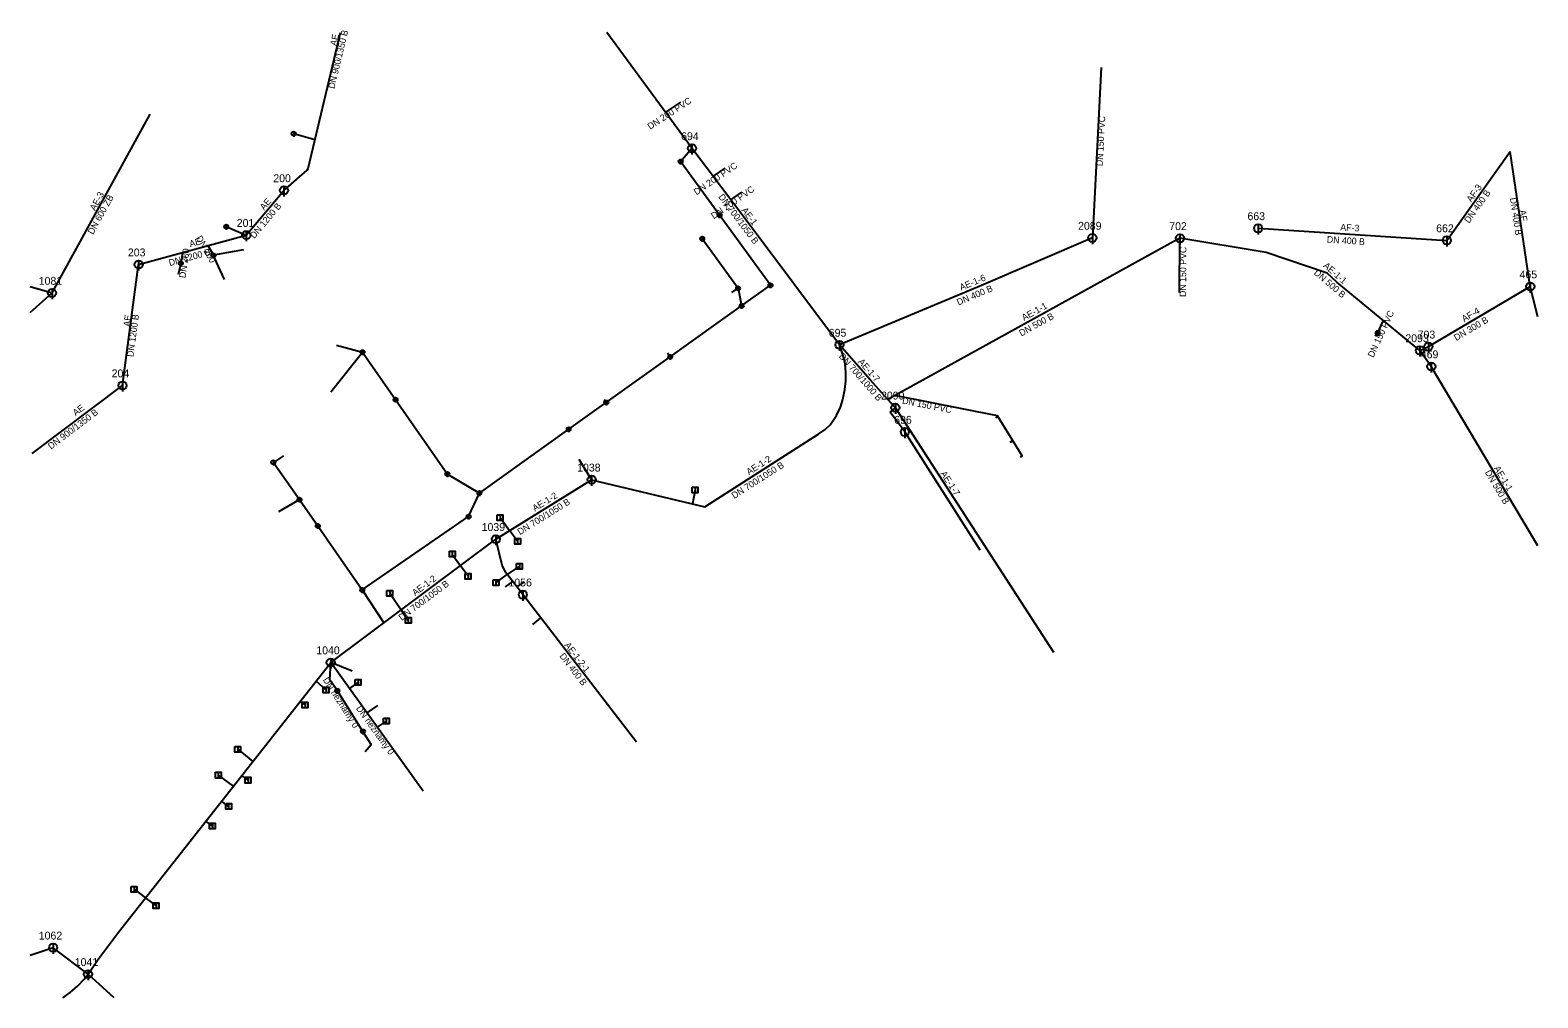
# Model space of a CAD drawing. Extents: x -4927513 to -4923824, y -11264917 to -11262549.
import ezdxf

# ---------------------------------------------------------------- set-up
doc = ezdxf.new("R2010")
doc.units = 0
for name, color, linetype in [('_pripojka_kanal_destova_priblizne_', 7, 'Continuous'), ('_pripojka_kanal_jednotna_prevzato_z_dokumentace_', 7, 'Continuous'), ('_pripojka_kanal_jednotna_priblizne_', 7, 'Continuous'), ('_pripojka_kanal_splaskova_priblizne_', 7, 'Continuous'), ('_stoka_jednotna_smvak_prevzato_z_dokumentace_', 7, 'Continuous'), ('_stoka_jednotna_smvak_priblizne_', 7, 'Continuous'), ('Default', 7, 'Continuous'), ('MoLevel 1', 7, 'Continuous'), ('MoLevel 119', 7, 'Continuous'), ('MoLevel 120', 7, 'Continuous'), ('MoLevel 124', 7, 'Continuous'), ('MoLevel 126', 7, 'Continuous'), ('MoLevel 2', 7, 'Continuous'), ('MoLevel 57', 7, 'Continuous'), ('MoLevel 60', 7, 'Continuous'), ('MoLevel 63', 7, 'Continuous'), ('MoLevel 68', 7, 'Continuous'), ('MoLevel 69', 7, 'Continuous')]:
    doc.layers.add(name, color=color, linetype=linetype)

# ---------------------------------------------------------------- blocks, each defined once
blk = doc.blocks.new('_vpust_')
at = {"layer": 'Default'}
blk.add_line((0, 0.00025), (0, -0.00025), dxfattribs=at)
blk.add_lwpolyline([(-0.00035, 0.00035), (0.00035, 0.00035), (0.00035, -0.00035), (-0.00035, -0.00035), (-0.00035, 0.00035)], dxfattribs=at)
blk = doc.blocks.new('_sachta_kanal_prip_')
at = {"layer": 'Default'}
blk.add_line((0, 0.0005), (0, -0.00075), dxfattribs=at)
blk.add_circle((0, 0), 0.0005, dxfattribs=at)
blk = doc.blocks.new('_sachta_kanal_prevzato_z_dokumentace_')
at = {"layer": 'Default'}
blk.add_line((0, 0.0005), (0, -0.00075), dxfattribs=at)
blk.add_circle((0, 0), 0.0005, dxfattribs=at)

msp = doc.modelspace()

# ---------------------------------------------------------------- linework, layer by layer
at = {"layer": '_pripojka_kanal_destova_priblizne_'}
for p, q in [((-4925150.4, -11263497.6), (-4925146, -11263492.5)), ((-4926170.4, -11263598.6), (-4926139.5, -11263648.9)), ((-4925886.4, -11263673.9), (-4925892.7, -11263708)), ((-4926363.5, -11263741.6), (-4926340.1, -11263773.6)), ((-4926320.6, -11263799.5), (-4926340.1, -11263773.6)), ((-4926480.6, -11263831), (-4926460.5, -11263859.3)), ((-4926441.7, -11263885.2), (-4926460.5, -11263859.3)), ((-4926373.5, -11263900.9), (-4926345.8, -11263880.7)), ((-4926316.3, -11263860.9), (-4926345.8, -11263880.7)), ((-4926633.4, -11263926.9), (-4926605.7, -11263967.6)), ((-4926588, -11263993.1), (-4926605.7, -11263967.6)), ((-4926725.7, -11264117.3), (-4926777.9, -11264096.1)), ((-4926789.4, -11264163.8), (-4926813.9, -11264141.9)), ((-4926710.9, -11264144.6), (-4926732.2, -11264159.7)), ((-4926840.6, -11264200.2), (-4926852.4, -11264190.8)), ((-4926641.9, -11264239.5), (-4926664.3, -11264254.2)), ((-4927005.6, -11264308.5), (-4926968.5, -11264338.2)), ((-4927053.1, -11264371.9), (-4927016.3, -11264399)), ((-4926980.3, -11264384.2), (-4926995.7, -11264372.8)), ((-4927027.9, -11264448.4), (-4927045, -11264435.3)), ((-4927067.4, -11264496.4), (-4927083.6, -11264484.4)), ((-4927259.1, -11264651.2), (-4927231.4, -11264672.2)), ((-4927205.4, -11264691.2), (-4927231.4, -11264672.2))]:
    msp.add_line(p, q, dxfattribs=at)
at = {"layer": '_pripojka_kanal_jednotna_prevzato_z_dokumentace_'}
for p, q in [((-4927033.6, -11263029.7), (-4926984.4, -11263050.4)), ((-4927078.7, -11263076.2), (-4927065.1, -11263099.9)), ((-4927141, -11263093.2), (-4927144.6, -11263119.7))]:
    msp.add_line(p, q, dxfattribs=at)
at = {"layer": '_pripojka_kanal_jednotna_priblizne_'}
for p, q in [((-4924892.2, -11262639.9), (-4924914.1, -11263057.3)), ((-4925922.3, -11262725.5), (-4925958.9, -11262749.5)), ((-4926868.5, -11262802.2), (-4926816.6, -11262816.8)), ((-4925921.6, -11262870.2), (-4925893.8, -11262838)), ((-4925826.2, -11263001.7), (-4925921.6, -11262870.2)), ((-4925813.4, -11262886.8), (-4925842.3, -11262906.5)), ((-4925772.8, -11262945.5), (-4925799.2, -11262963.8)), ((-4925701.8, -11263173.1), (-4925826.2, -11263001.7)), ((-4925868.7, -11263059), (-4925781, -11263180.4)), ((-4924700.7, -11263190.8), (-4924699.8, -11263058.1)), ((-4927144.6, -11263119.7), (-4927150.9, -11263147.2)), ((-4925796.5, -11263191.1), (-4925781, -11263180.4)), ((-4925781, -11263180.4), (-4925772.3, -11263223.4)), ((-4925772.3, -11263223.4), (-4925701.8, -11263173.1)), ((-4925947.1, -11263348.2), (-4925772.3, -11263223.4)), ((-4924222.1, -11263296.6), (-4924215.7, -11263289.5)), ((-4926777.8, -11263434.1), (-4926700.1, -11263336.6)), ((-4926763.4, -11263319.4), (-4926700.1, -11263336.6)), ((-4926700.1, -11263336.6), (-4926619.1, -11263452.9)), ((-4925953.9, -11263338.5), (-4925947.1, -11263348.2)), ((-4926103.5, -11263459.8), (-4925947.1, -11263348.2)), ((-4926195.4, -11263525.4), (-4926103.5, -11263459.8)), ((-4926109, -11263452.5), (-4926103.5, -11263459.8)), ((-4926414.1, -11263681.5), (-4926195.4, -11263525.4)), ((-4926893.4, -11263590.8), (-4926918.3, -11263606.5)), ((-4926918.3, -11263606.5), (-4926854.2, -11263697.6)), ((-4926492.3, -11263635), (-4926414.1, -11263681.5)), ((-4926904.7, -11263727.1), (-4926854.2, -11263697.6)), ((-4926854.2, -11263697.6), (-4926809.4, -11263762)), ((-4926700.8, -11263918.8), (-4926440.4, -11263739.1)), ((-4926809.4, -11263762), (-4926700.8, -11263918.8)), ((-4926700.8, -11263918.8), (-4926647.8, -11263999)), ((-4926349.9, -11263911.4), (-4926332.2, -11263898.1)), ((-4926304.1, -11263898.6), (-4926322.1, -11263911.4)), ((-4926283.2, -11264003), (-4926263.8, -11263987.2)), ((-4926551.5, -11264411.2), (-4926777.9, -11264096.1))]:
    msp.add_line(p, q, dxfattribs=at)
for points in [[(-4926991.2, -11263086.2), (-4927028.1, -11263092.6), (-4927065.1, -11263099.9)], [(-4927037.8, -11263158.7), (-4927057.5, -11263116.8), (-4927065.1, -11263099.9)], [(-4924215.7, -11263289.5), (-4924208.3, -11263273.2), (-4924201.7, -11263259.2)], [(-4925090.1, -11263592.8), (-4925086, -11263590.2), (-4925146, -11263492.5), (-4925397.1, -11263442.9)], [(-4926619.1, -11263452.9), (-4926492.4, -11263635), (-4926492.3, -11263635)], [(-4926440.4, -11263739.1), (-4926440.4, -11263739.1), (-4926414.1, -11263681.5)]]:
    msp.add_lwpolyline(points, dxfattribs=at)
at = {"layer": '_pripojka_kanal_splaskova_priblizne_'}
for p, q in [((-4925115.6, -11263556.7), (-4925108.8, -11263553.1)), ((-4926699, -11264264.8), (-4926761.7, -11264165.4)), ((-4926663.7, -11264201.2), (-4926689.3, -11264219.4))]:
    msp.add_line(p, q, dxfattribs=at)
for points in [[(-4926761.7, -11264165.4), (-4926779.9, -11264139), (-4926777.9, -11264096.1)], [(-4926693.9, -11264314.2), (-4926678.7, -11264297), (-4926699, -11264264.8)]]:
    msp.add_lwpolyline(points, dxfattribs=at)
at = {"layer": '_stoka_jednotna_smvak_prevzato_z_dokumentace_'}
for p, q in [((-4925893.8, -11262838), (-4926102.1, -11262554.7)), ((-4927459.8, -11263192), (-4927220.1, -11262754.5)), ((-4924046.6, -11263063.4), (-4923891.9, -11262845.8)), ((-4923842.4, -11263176.3), (-4923891.9, -11262845.8)), ((-4926984.4, -11263050.4), (-4926892.3, -11262940.9)), ((-4924508.3, -11263033.8), (-4924046.6, -11263063.4)), ((-4927248, -11263122.4), (-4926984.4, -11263050.4)), ((-4927287.4, -11263418.4), (-4927248, -11263122.4)), ((-4927513.4, -11263176.3), (-4927459.8, -11263192)), ((-4927513.4, -11263240.1), (-4927459.8, -11263192)), ((-4923823.9, -11263250.2), (-4923842.4, -11263176.3)), ((-4924084.6, -11263371.8), (-4924112.8, -11263332.4)), ((-4923823.9, -11263810.7), (-4924084.6, -11263371.8)), ((-4927508.4, -11263584.9), (-4927287.4, -11263418.4)), ((-4925372.9, -11263532), (-4925408.8, -11263483.9)), ((-4925188.6, -11263821.2), (-4925372.9, -11263532)), ((-4926373.7, -11263794.5), (-4926139.5, -11263648.9)), ((-4926777.9, -11264096.1), (-4926373.7, -11263794.5)), ((-4926029.8, -11264291), (-4926307.7, -11263930.1)), ((-4927457, -11264794.1), (-4927513.4, -11264813.2)), ((-4927371.7, -11264858.9), (-4927457, -11264794.1)), ((-4927371.7, -11264858.9), (-4927348.8, -11264824.4)), ((-4927307.6, -11264916.8), (-4927371.7, -11264858.9))]:
    msp.add_line(p, q, dxfattribs=at)
for points in [[(-4925533, -11263319), (-4925756.6, -11263020.4), (-4925893.8, -11262838)], [(-4926892.3, -11262940.9), (-4926835.8, -11262891.7), (-4926833.3, -11262887.3)], [(-4924914.1, -11263057.3), (-4925190.7, -11263175.8), (-4925533, -11263319)], [(-4926307.7, -11263930.1), (-4926349.9, -11263875.1), (-4926358.5, -11263858.4), (-4926373.7, -11263794.5)], [(-4927348.8, -11264824.4), (-4927297.3, -11264755.9), (-4926777.9, -11264096.1)], [(-4927433.5, -11264916.8), (-4927415.7, -11264904.1), (-4927396.7, -11264887.4), (-4927381, -11264870.9), (-4927371.7, -11264858.9)]]:
    msp.add_lwpolyline(points, dxfattribs=at)
at = {"layer": '_stoka_jednotna_smvak_priblizne_'}
for p, q in [((-4926833.3, -11262887.3), (-4926754.3, -11262554.7)), ((-4924699.8, -11263058.1), (-4925414.7, -11263452.6)), ((-4924091.8, -11263323.4), (-4923842.4, -11263176.3)), ((-4924112.8, -11263332.4), (-4924091.8, -11263323.4)), ((-4925396, -11263472.8), (-4925414.7, -11263452.6)), ((-4925408.8, -11263483.9), (-4925396, -11263472.8)), ((-4925008.4, -11264071.9), (-4925396, -11263472.8))]:
    msp.add_line(p, q, dxfattribs=at)
for points in [[(-4924112.8, -11263332.4), (-4924315.7, -11263165.3), (-4924339.8, -11263143.6), (-4924488.9, -11263093), (-4924699.8, -11263058.1)], [(-4926139.5, -11263648.9), (-4925862.7, -11263715.2), (-4925583.1, -11263536.8), (-4925567.7, -11263526.3), (-4925555.6, -11263514.6), (-4925540.1, -11263492.1), (-4925530.4, -11263471.4), (-4925524.3, -11263452.7), (-4925519.6, -11263428.3), (-4925517.3, -11263406.9), (-4925517.1, -11263388), (-4925518.4, -11263374.3), (-4925520, -11263359.5), (-4925522.9, -11263348.6), (-4925526.4, -11263337.7), (-4925533, -11263319)], [(-4925414.7, -11263452.6), (-4925430.4, -11263435.6), (-4925456.7, -11263405.4), (-4925533, -11263319)]]:
    msp.add_lwpolyline(points, dxfattribs=at)

# ---------------------------------------------------------------- block references
at = {"layer": 'MoLevel 119', "xscale": 20000, "yscale": 20000}
for p in [(-4925893.8, -11262838), (-4926892.3, -11262940.9), (-4926984.4, -11263050.4), (-4924508.3, -11263033.8), (-4924914.1, -11263057.3), (-4924699.8, -11263058.1), (-4924046.6, -11263063.4), (-4927248, -11263122.4), (-4927459.8, -11263192), (-4923842.4, -11263176.3), (-4925533, -11263319), (-4924112.8, -11263332.4), (-4924091.8, -11263323.4), (-4924084.6, -11263371.8), (-4927287.4, -11263418.4), (-4925396, -11263472.8), (-4925372.9, -11263532), (-4926139.5, -11263648.9), (-4926373.7, -11263794.5), (-4926307.7, -11263930.1), (-4926777.9, -11264096.1), (-4927457, -11264794.1), (-4927371.7, -11264858.9)]:
    msp.add_blockref('_sachta_kanal_prevzato_z_dokumentace_', p, dxfattribs=at)
at = {"layer": 'MoLevel 57', "xscale": 10000, "yscale": 10000}
for p in [(-4926868.5, -11262802.2), (-4925921.6, -11262870.2), (-4925826.2, -11263001.7), (-4927033.6, -11263029.7), (-4925868.7, -11263059), (-4927144.6, -11263119.7), (-4927065.1, -11263099.9), (-4925781, -11263180.4), (-4925701.8, -11263173.1), (-4925772.3, -11263223.4), (-4924215.7, -11263289.5), (-4926700.1, -11263336.6), (-4925947.1, -11263348.2), (-4926619.1, -11263452.9), (-4926103.5, -11263459.8), (-4926195.4, -11263525.4), (-4926918.3, -11263606.5), (-4926492.4, -11263635), (-4926854.2, -11263697.6), (-4926414.1, -11263681.5), (-4926440.4, -11263739.1), (-4926809.4, -11263762), (-4926700.8, -11263918.8), (-4926761.7, -11264165.4), (-4926699, -11264264.8)]:
    msp.add_blockref('_sachta_kanal_prip_', p, dxfattribs=at)
at = {"layer": 'MoLevel 63', "xscale": 20000, "yscale": 20000}
for p in [(-4925886.4, -11263673.9), (-4926363.5, -11263741.6), (-4926320.6, -11263799.5), (-4926480.6, -11263831), (-4926316.3, -11263860.9), (-4926441.7, -11263885.2), (-4926373.5, -11263900.9), (-4926633.4, -11263926.9), (-4926588, -11263993.1), (-4926710.9, -11264144.6), (-4926789.4, -11264163.8), (-4926840.6, -11264200.2), (-4926641.9, -11264239.5), (-4927005.6, -11264308.5), (-4927053.1, -11264371.9), (-4926980.3, -11264384.2), (-4927027.9, -11264448.4), (-4927067.4, -11264496.4), (-4927259.1, -11264651.2), (-4927205.4, -11264691.2)]:
    msp.add_blockref('_vpust_', p, dxfattribs=at)

# ---------------------------------------------------------------- texts
at = {"layer": 'MoLevel 1'}
for s, height, rotation, p in [('DN 900/1350 B', 16.049, 76.6384, (-4926768.9, -11262693.5)), ('DN 500 B', 16.05, 319.2298, (-4924373.3, -11263144.8)), ('DN 500 B', 16.05, 28.886, (-4925087.9, -11263298.6)), ('DN 500 B', 16.05, 28.886, (-4925087.9, -11263298.6)), ('DN 500 B', 16.05, 28.886, (-4925087.9, -11263298.6)), ('DN 300 B', 16.05, 30.5284, (-4924023.5, -11263309.8)), ('DN 300 B', 16.05, 30.5284, (-4924023.5, -11263309.8)), ('DN 300 B', 16.05, 30.5284, (-4924023.5, -11263309.8)), ('DN 700/1000 B', 16.049, 311.2445, (-4925535.5, -11263347.8)), ('DN 700/1000 B', 16.049, 311.2445, (-4925535.5, -11263347.8)), ('DN 700/1000 B', 16.049, 311.2445, (-4925535.5, -11263347.8)), ('DN 700/1050 B', 16.049, 32.5434, (-4925790.6, -11263696.2))]:
    msp.add_text(s, height=height, rotation=rotation, dxfattribs=at).set_placement(p)
at = {"layer": 'MoLevel 120'}
for s, p in [('694', (-4925920.4, -11262818)), ('200', (-4926918.4, -11262920.9)), ('663', (-4924534.5, -11263013.8)), ('201', (-4927007.8, -11263030.4)), ('2089', (-4924949, -11263037.3)), ('702', (-4924725.9, -11263038.1)), ('662', (-4924072.7, -11263043.4)), ('203', (-4927274.2, -11263102.4)), ('1081', (-4927492.4, -11263172)), ('465', (-4923868.6, -11263156.3)), ('695', (-4925559.1, -11263299)), ('2093', (-4924148.1, -11263312.4)), ('703', (-4924118, -11263303.4)), ('469', (-4924110.3, -11263351.8)), ('204', (-4927314, -11263398.4)), ('2090', (-4925431.3, -11263452.8)), ('696', (-4925399, -11263512)), ('1038', (-4926174.8, -11263628.9)), ('1039', (-4926408.6, -11263774.5)), ('1056', (-4926343, -11263910.1)), ('1040', (-4926813.2, -11264076.1)), ('1062', (-4927492.3, -11264774.1)), ('1041', (-4927404.3, -11264838.9))]:
    msp.add_text(s, height=19.26, dxfattribs=at).set_placement(p)
at = {"layer": 'MoLevel 124'}
for s, height, rotation, p in [('DN 200 PVC', 16.05, 33.2462, (-4925996.2, -11262793.1)), ('DN 150 PVC', 16.05, 87.0017, (-4924888.8, -11262882)), ('DN 200 PVC', 16.05, 34.2629, (-4925882.7, -11262953.4)), ('DN 200 PVC', 16.05, 34.7756, (-4925840.4, -11263012)), ('DN 150 PVC', 16.05, 89.6329, (-4924684.7, -11263201.8)), ('DN 150 PVC', 16.05, 65.2911, (-4924226.5, -11263351.4)), ('DN 150 PVC', 16.05, 348.8177, (-4925380.5, -11263462.5)), ('DN neznámý 0', 16.049, 305.6996, (-4926716.8, -11264208.7))]:
    msp.add_text(s, height=height, rotation=rotation, dxfattribs=at).set_placement(p)
at = {"layer": 'MoLevel 126'}
for rotation, p in [(299.904, (-4927108.1, -11263057.4)), (82.4391, (-4927133.1, -11263156.3))]:
    msp.add_text('DN 200', height=16.05, rotation=rotation, dxfattribs=at).set_placement(p)
at = {"layer": 'MoLevel 2'}
for s, rotation, p in [('AE', 76.6384, (-4926764.2, -11262588.3)), ('AE-1-1', 319.2298, (-4924350.4, -11263127.4)), ('AE-1-1', 28.886, (-4925081.3, -11263260.6)), ('AE-1-1', 28.886, (-4925081.3, -11263260.6)), ('AE-1-1', 28.886, (-4925081.3, -11263260.6)), ('AF-4', 30.5284, (-4924004.3, -11263263.8)), ('AE-1-7', 311.2445, (-4925488.4, -11263361.2)), ('AE-1-7', 311.2445, (-4925488.4, -11263361.2)), ('AE-1-7', 311.2445, (-4925488.4, -11263361.2)), ('AE-1-2', 32.5434, (-4925754.4, -11263638.1)), ('AE-1-7', 302.9009, (-4925286.5, -11263634))]:
    msp.add_text(s, height=16.05, rotation=rotation, dxfattribs=at).set_placement(p)
at = {"layer": 'MoLevel 60'}
msp.add_text('DN neznámý 0', height=16.049, rotation=302.2304, dxfattribs=at).set_placement((-4926797.6, -11264138.6))
at = {"layer": 'MoLevel 68'}
for s, height, rotation, p in [('DN 600 ZB', 16.05, 61.2791, (-4927359.5, -11263050.3)), ('DN 1200 B', 16.05, 49.9524, (-4926964.9, -11263060.3)), ('DN 700/1050 B', 16.049, 306.8886, (-4925830.2, -11262957)), ('DN 700/1050 B', 16.049, 306.8886, (-4925830.2, -11262957)), ('DN 700/1050 B', 16.049, 306.8886, (-4925830.2, -11262957)), ('DN 400 B', 16.05, 54.5933, (-4923992.3, -11263022.7)), ('DN 400 B', 16.05, 278.5144, (-4923892.3, -11262959.9)), ('DN 400 B', 16.05, 356.3385, (-4924340.6, -11263068.7)), ('DN 1200 B', 16.05, 15.2704, (-4927171.9, -11263126.3)), ('DN 400 B', 16.05, 22.943, (-4925241.8, -11263222.9)), ('DN 400 B', 16.05, 22.943, (-4925241.8, -11263222.9)), ('DN 400 B', 16.05, 22.943, (-4925241.8, -11263222.9)), ('DN 1200 B', 16.05, 82.4198, (-4927261, -11263349.3)), ('DN 900/1350 B', 16.049, 36.997, (-4927462.5, -11263575.5)), ('DN 500 B', 16.05, 300.7063, (-4923954.1, -11263631)), ('DN 700/1050 B', 16.049, 31.8688, (-4926314.9, -11263784.9)), ('DN 700/1050 B', 16.049, 36.729, (-4926604.4, -11263994.7)), ('DN 400 B', 16.05, 307.597, (-4926219, -11264080.8))]:
    msp.add_text(s, height=height, rotation=rotation, dxfattribs=at).set_placement(p)
at = {"layer": 'MoLevel 69'}
for s, rotation, p in [('AF-3', 54.5933, (-4923986.7, -11262971.2)), ('AE-3', 61.2791, (-4927354.7, -11262992)), ('AE', 49.9524, (-4926940.8, -11262990.6)), ('AE-1', 306.8886, (-4925773.6, -11262989.8)), ('AE-1', 306.8886, (-4925773.6, -11262989.8)), ('AE-1', 306.8886, (-4925773.6, -11262989.8)), ('AE-1', 306.8886, (-4925773.6, -11262989.8)), ('AF', 278.5144, (-4923869.2, -11262989.9)), ('AF-3', 356.3385, (-4924307.6, -11263038.7)), ('AE', 15.2704, (-4927121.5, -11263079.9)), ('AE-1-6', 22.943, (-4925235, -11263186.6)), ('AE-1-6', 22.943, (-4925235, -11263186.6)), ('AE-1-6', 22.943, (-4925235, -11263186.6)), ('AE', 82.4198, (-4927269.4, -11263275.1)), ('AE', 36.997, (-4927401.9, -11263493.7)), ('AE-1-1', 300.7063, (-4923931.9, -11263620.9)), ('AE-1-2', 31.8688, (-4926278.3, -11263727.2)), ('AE-1-2', 36.729, (-4926571.4, -11263934)), ('AE-1-2-1', 307.597, (-4926207, -11264054.1))]:
    msp.add_text(s, height=16.05, rotation=rotation, dxfattribs=at).set_placement(p)

doc.saveas('drawing.dxf')
